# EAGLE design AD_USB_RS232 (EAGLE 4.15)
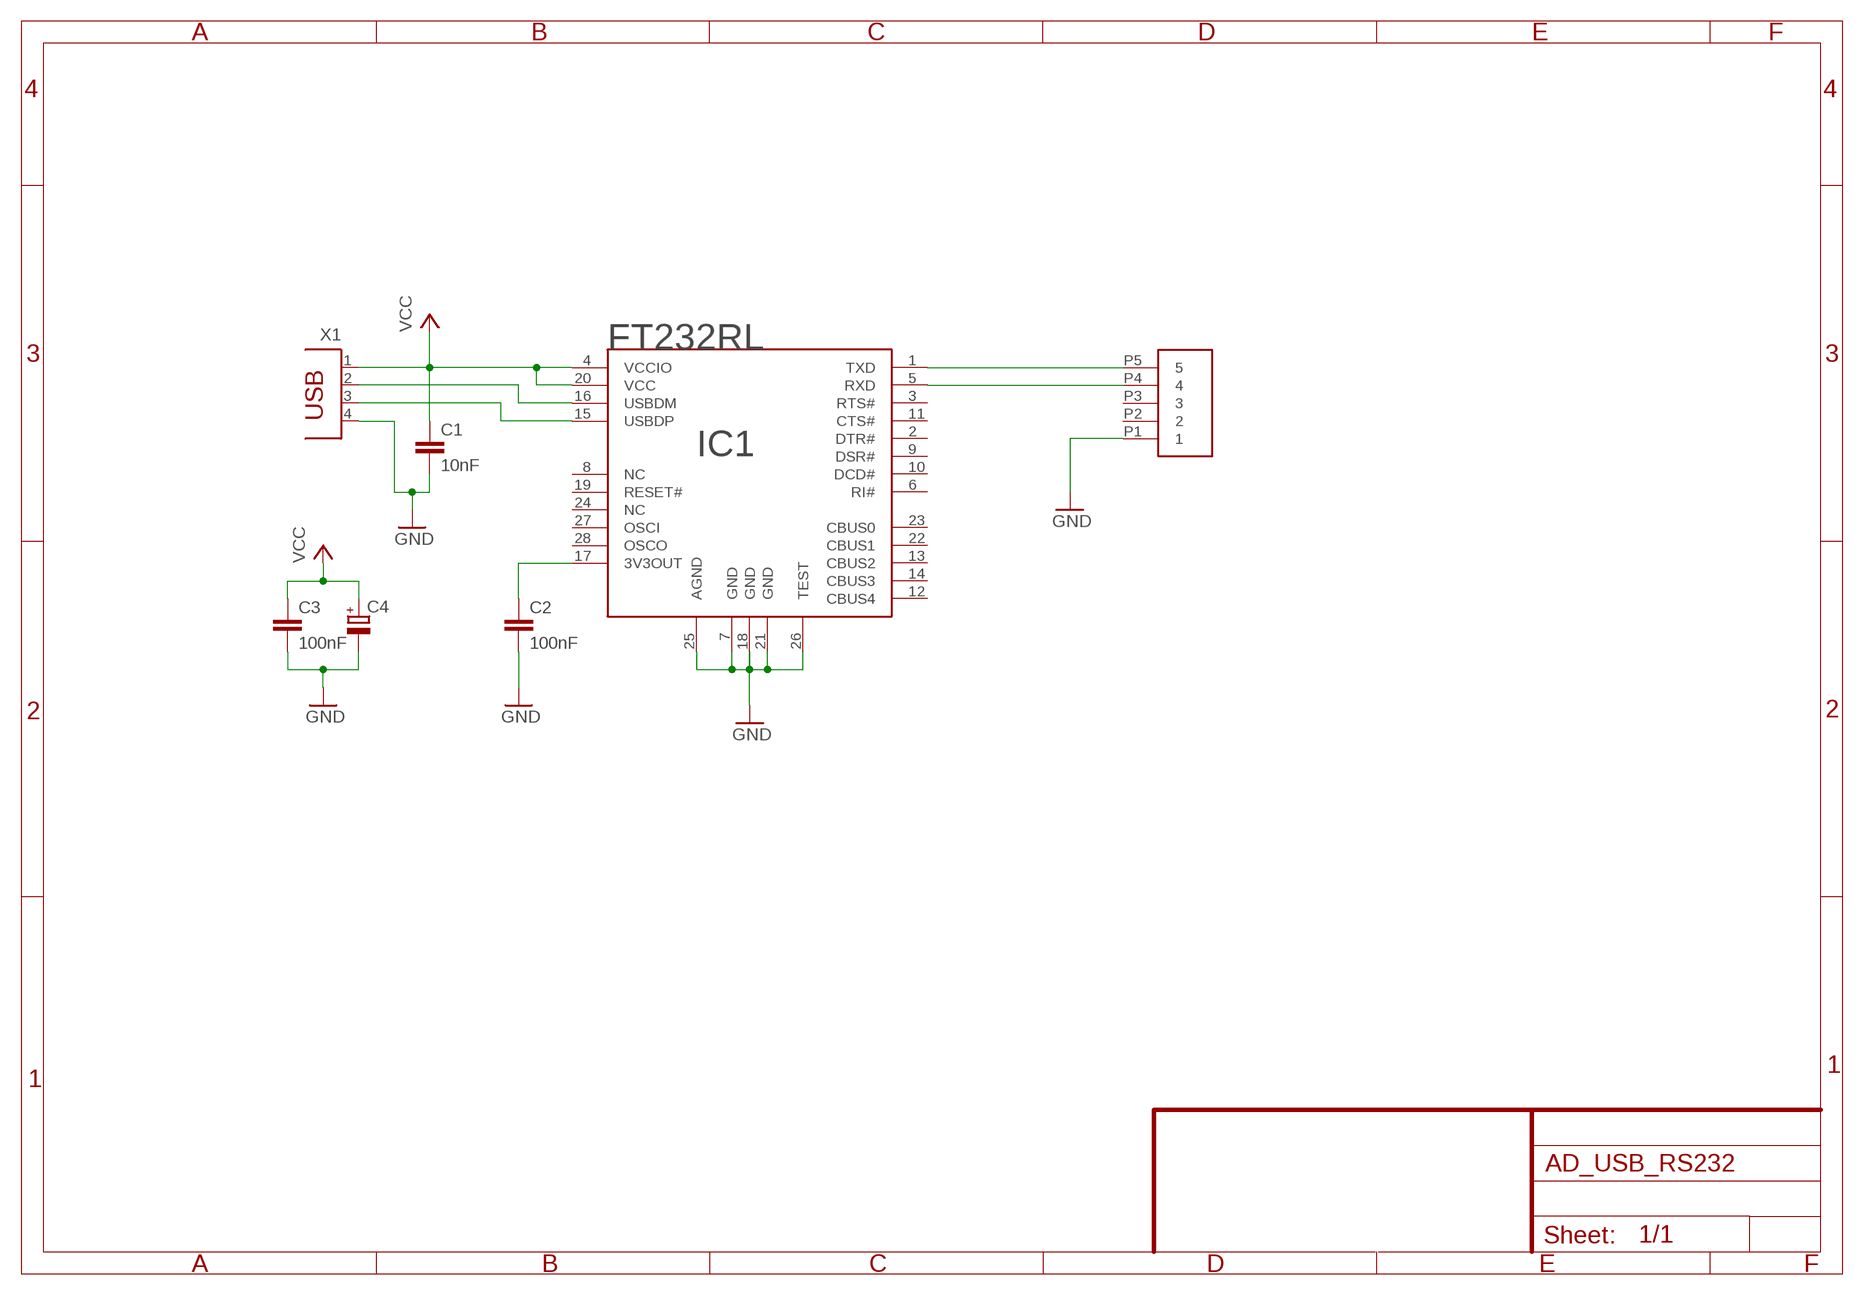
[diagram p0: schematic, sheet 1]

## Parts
C1  10nF  C-EUC0805  [C0805]
C2  100nF  C-EUC0805  [C0805]
C3  100nF  C-EUC0805  [C0805]
C4  CPOL-EU085CS-1AR  [085CS_1AR]
CON2  RS_CON_F  [F80-614-5]
IC1  FT232RL  [SSOP28]
X1  PN61729  [PN61729]

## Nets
GND: C1.2 C2.2 C3.2 C4.- CON2.P1 IC1.7(GND) IC1.18(GND) IC1.21(GND) IC1.25(AGND) IC1.26(TEST) X1.4
N$1: IC1.16(USBDM) X1.2
N$2: IC1.15(USBDP) X1.3
N$4: CON2.P5 IC1.1(TXD)
N$5: C2.1 IC1.17(3V3OUT)
N$6: CON2.P4 IC1.5(RXD)
VCC: C1.1 C3.1 C4.+ IC1.4(VCCIO) IC1.20(VCC) X1.1
Unconnected: CON2.P2 CON2.P3 IC1.2(DTR#) IC1.3(RTS#) IC1.6(RI#) IC1.8(NC) IC1.9(DSR#) IC1.10(DCD#) IC1.11(CTS#) IC1.12(CBUS4) IC1.13(CBUS2) IC1.14(CBUS3) IC1.19(RESET#) IC1.22(CBUS1) IC1.23(CBUS0) IC1.24(NC) IC1.27(OSCI) IC1.28(OSCO)

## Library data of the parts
C1-C3 = rcl:C-EU: CAPACITOR, European symbol
C4 = rcl:CPOL-EU: POLARIZED CAPACITOR, European symbol
CON2 = FTDI:RS_CON_F
IC1 = FTDI:FT232RL
X1 = con-berg:PN61729: BERG USB connector

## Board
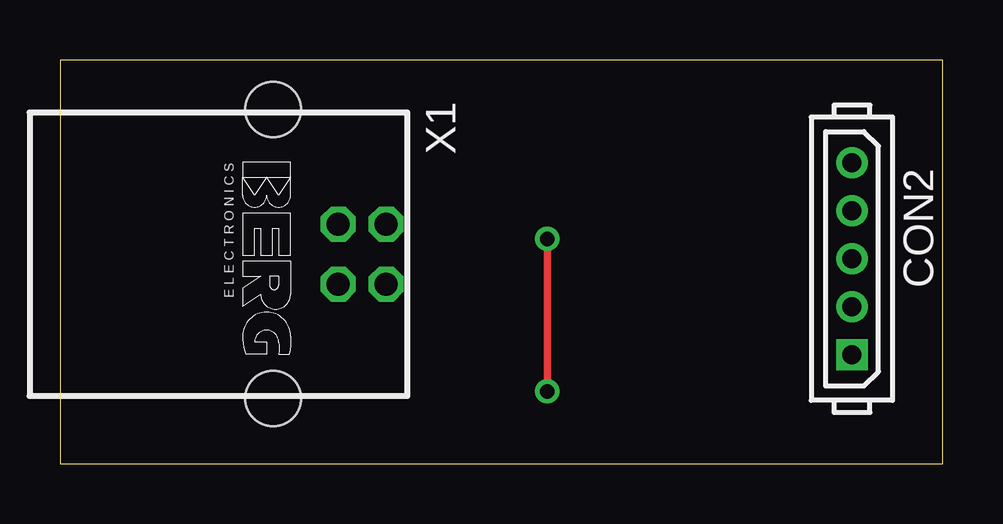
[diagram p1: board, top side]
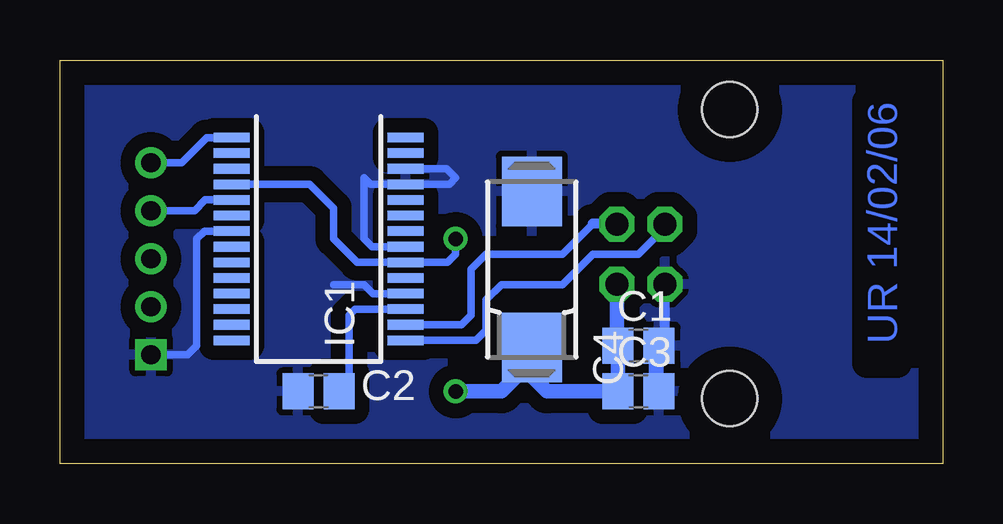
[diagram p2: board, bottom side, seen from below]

Size 36.81 x 16.82 mm. Coordinates in mm from the lower left corner, seen from the top.
Outline: 0,0 36.81,0 36.81,16.82 0,16.82 0,0
Copper layers (1*16): Top 0.035mm / dielectric 1.5mm / Bottom 0.035mm
Design rules "default": minimum track width 10mil, minimum drill 24mil, track to track 8mil, track to pad 8mil, pad to pad 8mil, via to via 8mil, smd to smd 8mil, copper to edge 40mil, drill to drill 8mil, minimum pad ring 10mil, minimum via ring 8mil, stop-mask expansion 4mil, vias tented up to drill 0mil, thermal gap 10mil

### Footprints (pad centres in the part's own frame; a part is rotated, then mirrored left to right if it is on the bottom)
C0805 = smd 1.3 x 1.5: 1 -0.85,0; 2 0.85,0
085CS_1AR = smd 2.9 x 2.5: + 3.25,0; - -3.25,0
F80-614-5 = drill 0.8 square: P1 8,0 | drill 0.8 round: P2 6,0; P3 4,0; P4 2,0; P5 0,0
SSOP28 = smd 0.4 x 1.5: 1 -4.225,-3.625; 2 -3.575,-3.625; 3 -2.925,-3.625; 4 -2.275,-3.625; 5 -1.625,-3.625; 6 -0.975,-3.625; 7 -0.325,-3.625; 8 0.325,-3.625; 9 0.975,-3.625; 10 1.625,-3.625; 11 2.275,-3.625; 12 2.925,-3.625; 13 3.575,-3.625; 14 4.225,-3.625; 15 4.225,3.625; 16 3.575,3.625; 17 2.925,3.625; 18 2.275,3.625; 19 1.625,3.625; 20 0.975,3.625; 21 0.325,3.625; 22 -0.325,3.625; 23 -0.975,3.625; 24 -1.625,3.625; 25 -2.275,3.625; 26 -2.925,3.625; 27 -3.575,3.625; 28 -4.225,3.625
PN61729 = drill 0.95 octagon: 1 1.25,4.71; 2 -1.25,4.71; 3 -1.25,2.71; 4 1.25,2.71 | hole 2.3: -6.02,0; 6.02,0

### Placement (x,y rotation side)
C1  12.7,4.92 0 bottom
C2  26.03,3.01 180 bottom
C3  12.7,3.01 0 bottom
C4  17.14,8.09 270 bottom
CON2  33.02,12.54 270 top
IC1  26.03,9.36 270 bottom
X1  8.89,8.72 270 top

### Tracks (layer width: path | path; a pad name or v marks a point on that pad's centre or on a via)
GND
  Bottom 0.305: IC1.7 30.79,9.69 31.11,9.36 31.11,4.92 31.49,4.54 CON2.P1 | IC1.26 20.7,12.29 20.31,11.9 20.58,11.63 IC1.25 23.86,11.63 24.12,11.9 24.12,9.36 23.8,9.04 IC1.21 | IC1.18 23.75,7.08 24.12,7.46 25.39,7.46
  Bottom 0.406: 12.06,4.92 C1.2 11.85,3.23 12.06,3.01 | X1.4 11.6,5.38 12.06,4.92 | C3.2 12.06,3.01 | 12.06,3.01 12.06,4.92
  pour Bottom (isolate 0.61): -0.01,16.98 36.83,16.98 36.83,0.47 -0.01,0.47
N$1
  Bottom 0.305: IC1.16 20.08,5.79 19.68,6.19 19.68,8.09 19.04,8.72 15.87,8.72 14.6,9.99 | X1.2 13.95,9.97
  Bottom 0.406: 13.95,9.97 13.97,9.99 14.6,9.99
N$2
  Bottom 0.305: IC1.15 19.46,5.13 19.04,5.55 19.04,6.82 18.41,7.46 15.87,7.46 14.6,8.72 12.7,8.72 11.45,9.97
  Bottom 0.406: 11.43,9.99 11.45,9.97 X1.3
N$4
  Bottom 0.305: CON2.P5 31.74,12.54 30.7,13.58 IC1.1
N$5
  Bottom 0.305: IC1.17 24.51,6.44 24.76,6.19 24.76,3.01 C2.1
N$6
  Bottom 0.305: IC1.5 30.75,10.98 31.2,10.54 CON2.P4
VCC  (via drill 0.6)
  Top 0.305: v20.31,3.01 v20.31,9.36
  Bottom 0.305: IC1.4 26.4,11.63 25.39,10.63 25.39,9.36 24.42,8.38 IC1.20 20.65,8.38 20.31,8.72 v20.31,9.36
  Bottom 0.406: 17.14,3.65 17.14,4.28 C4.+ | C1.1 13.33,4.92 13.6,5.18 | C3.1 13.33,3.01 13.54,3.23
  Bottom 0.61: C3.1 16.5,3.01 17.14,3.65 | 13.6,5.18 X1.1 | 13.54,3.23 C1.1 | 17.14,4.28 18.41,3.01 v20.31,3.01

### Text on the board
Bottom: UR 14/02/06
